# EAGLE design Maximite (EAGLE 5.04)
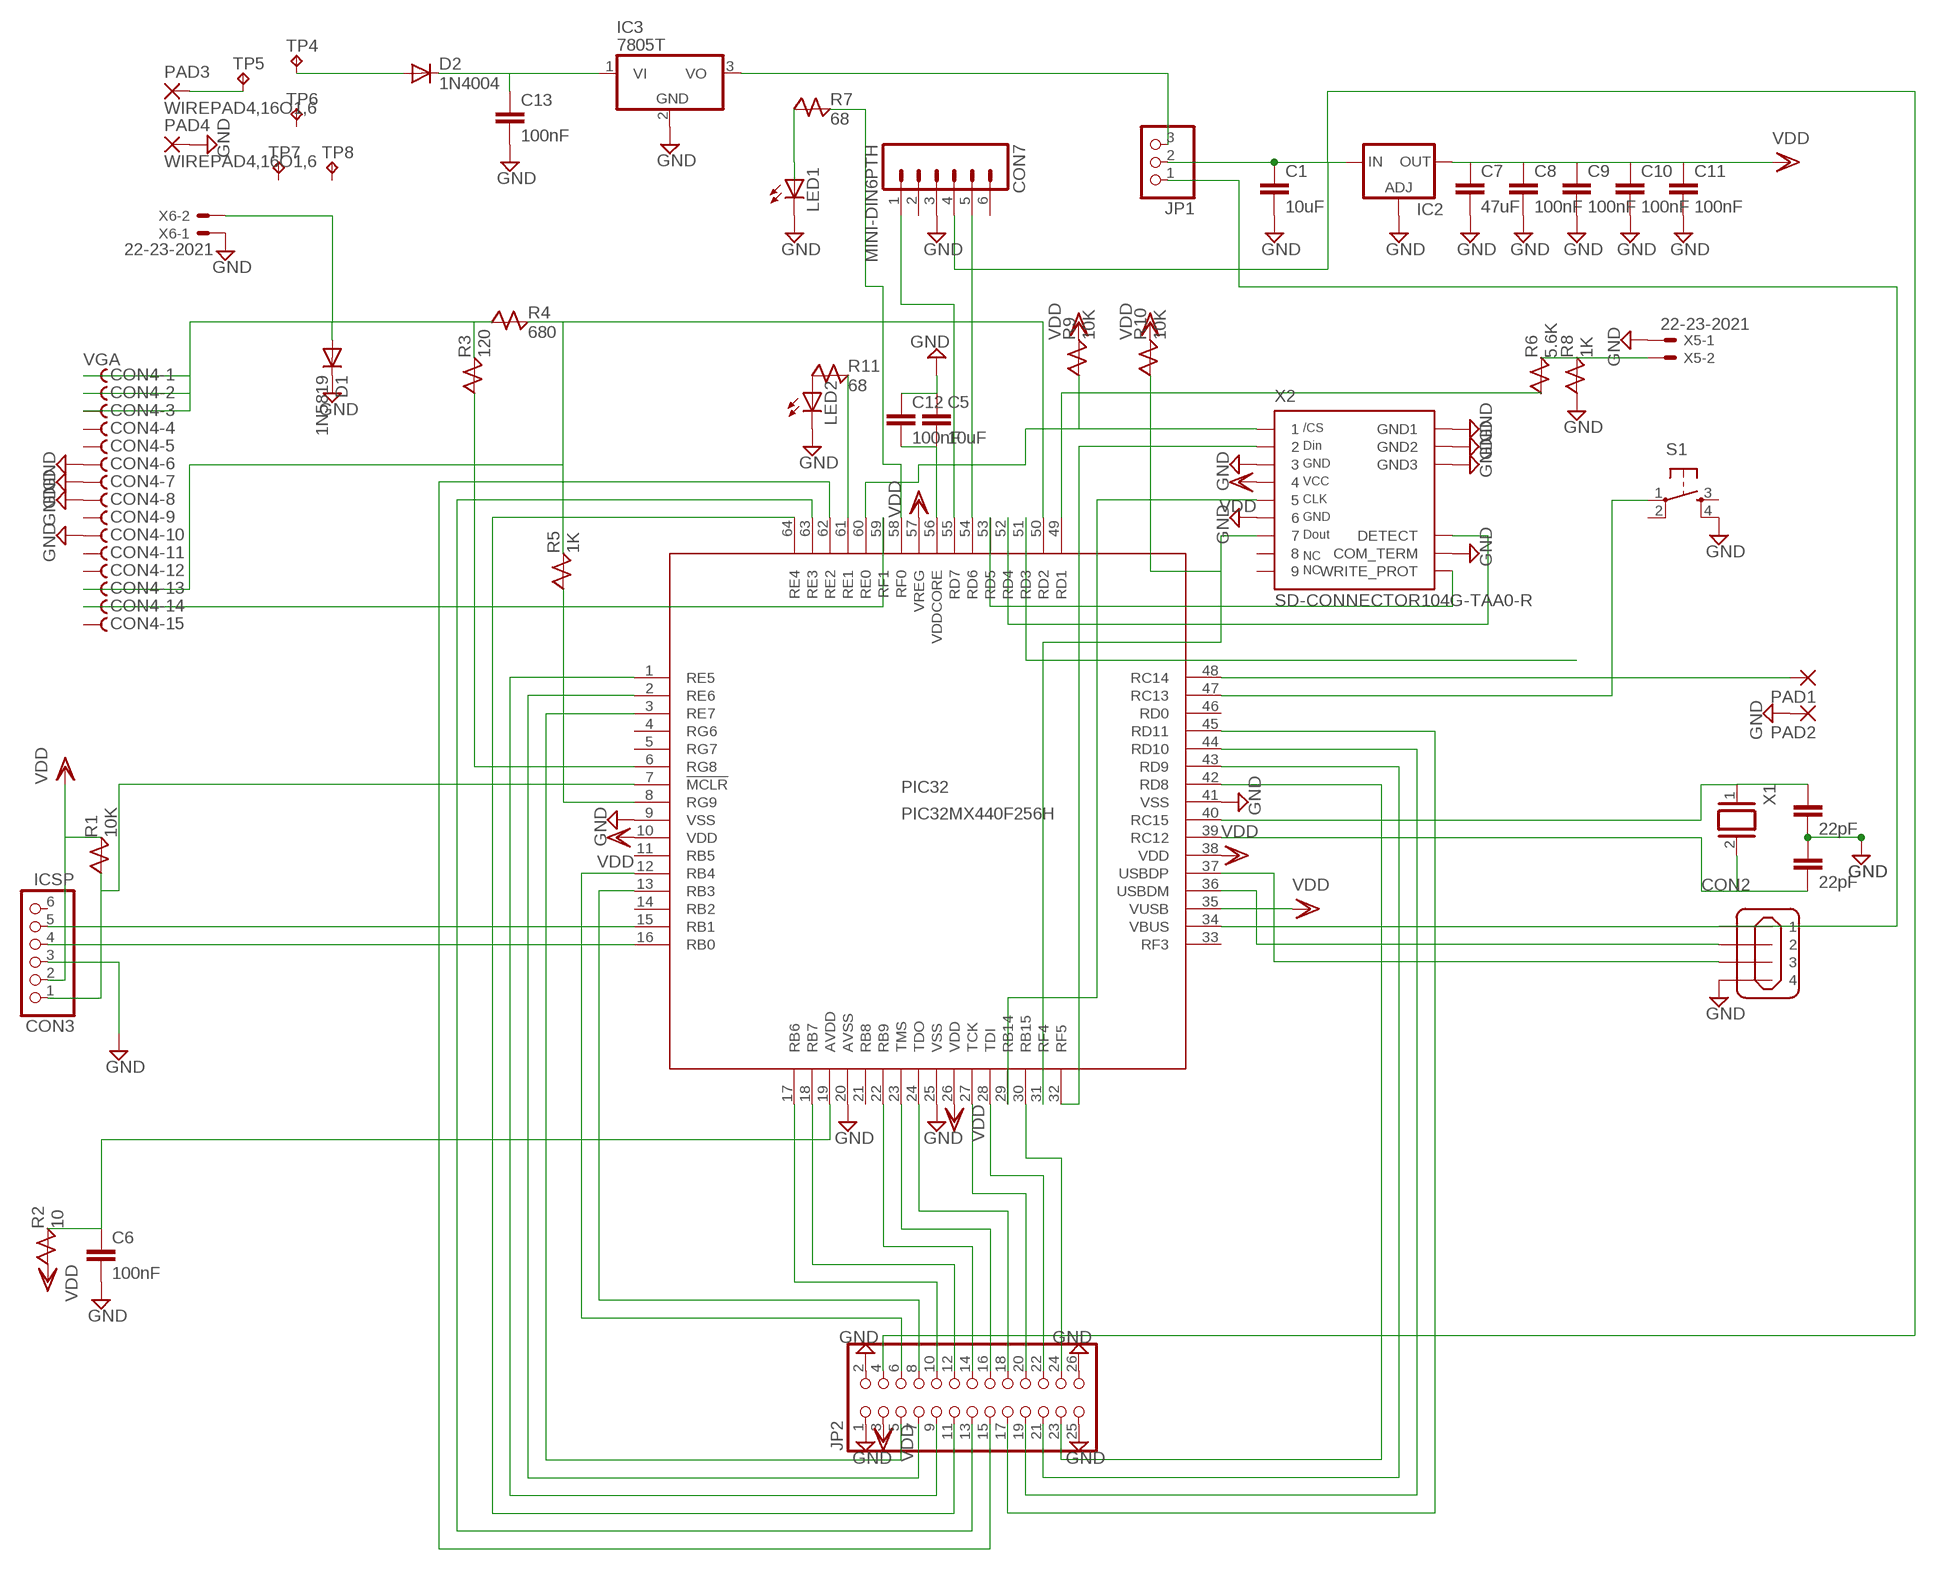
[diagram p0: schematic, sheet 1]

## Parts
C1  10uF  C5/2.5  [C5B2.5]
C3  22pF  C5/2.5  [C5B2.5]
C4  22pF  C5/2.5  [C5B2.5]
C5  10uF  C5/2.5  [C5B2.5]
C6  100nF  C5/2.5  [C5B2.5]
C7  47uF  C5/2.5  [C5B2.5]
C8  100nF  C5/2.5  [C5B2.5]
C9  100nF  C5/2.5  [C5B2.5]
C10  100nF  C5/2.5  [C5B2.5]
C11  100nF  C5/2.5  [C5B2.5]
C12  100nF  C5/2.5  [C5B2.5]
C13  100nF  C5/2.5  [C5B2.5]
CON2  MINI-USB_SHIELD4P-85-32004-10X  [85-32004-10X]
CON3  ICSP  PINHD-1X6  [1X06]
CON4  VGA  D-SUB15-HDR15RA  [HDR15RA]
CON7  MINI-DIN6PTH  [MINI-DIN6]
D1  1N5819  1N4148DO35-10  [DO35-10]
D2  1N4004  1N4148DO35-10  [DO35-10]
IC2  LM317TL  [317TL]
IC3  7805T  [TO220H]
JP1  PINHD-1X3  [1X03]
JP2  PINHD-2X13  [2X13]
LED1  LED3MM  [LED3MM]
LED2  LED3MM  [LED3MM]
PAD1  1,6/0,8  [1,6/0,8]
PAD2  1,6/0,8  [1,6/0,8]
PAD3  WIREPAD4,16O1,6  [4,16O1,6]
PAD4  WIREPAD4,16O1,6  [4,16O1,6]
PIC32  PIC32MX440F256H  [TQFP64-10X10]
R1  10K  1N4148DO35-10  [DO35-10]
R2  10  1N4148DO35-10  [DO35-10]
R3  120  1N4148DO35-10  [DO35-10]
R4  680  1N4148DO35-10  [DO35-10]
R5  1K  1N4148DO35-10  [DO35-10]
R6  5.6K  1N4148DO35-10  [DO35-10]
R7  68  1N4148DO35-10  [DO35-10]
R8  1K  1N4148DO35-10  [DO35-10]
R9  10K  1N4148DO35-10  [DO35-10]
R10  10K  1N4148DO35-10  [DO35-10]
R11  68  1N4148DO35-10  [DO35-10]
S1  TAC_SWITCHPTH  [TACTILE-PTH]
TP4  TPPAD1-13Y  [P1-13Y]
TP5  TPPAD1-13Y  [P1-13Y]
TP6  TPPAD1-13Y  [P1-13Y]
TP7  TPPAD1-17Y  [P1-17Y]
TP8  TPPAD1-17Y  [P1-17Y]
X1  XTAL/S  [QS]
X2  SD-CONNECTOR104G-TAA0-R  [104G-TAA0-R]
X5  22-23-2021  [22-23-2021]
X6  22-23-2021  [22-23-2021]

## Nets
GND: C1.2 C3.1 C4.2 C5.1 C6.2 C7.2 C8.2 C9.2 C10.2 C11.2 C12.1 C13.2 CON2.4 CON3.3 CON4.6 CON4.7 CON4.8 CON4.10 CON7.3 D1.C IC2.1(ADJ) IC3.2(GND) JP2.1 JP2.2 JP2.25 JP2.26 LED1.K(C) LED2.K(C) PAD2.1(P) PAD4.1(P) PIC32.9(VSS) PIC32.20(AVSS) PIC32.25(VSS) PIC32.41(VSS) R8.A S1.4 X2.3 X2.6 X2.COMMON(COM_TERM) X2.GND1 X2.GND2 X2.GND3 X5.1 X6.1
N$1: C3.2 PIC32.39(RC12) X1.2
N$2: CON2.1 JP1.1 PIC32.34(VBUS)
N$3: CON2.2 PIC32.36(USBDM)
N$4: CON2.3 PIC32.37(USBDP)
N$5: CON7.1 PIC32.55(RD7)
N$6: CON3.5 PIC32.15(RB1)
N$7: CON3.4 PIC32.16(RB0)
N$8: CON3.1 PIC32.7(!MCLR) R1.A
N$9: PIC32.47(RC13) S1.1
N$10: C5.2 C12.2 PIC32.56(VDDCORE)
N$11: PIC32.6(RG8) R3.A
N$12: C6.1 PIC32.19(AVDD) R2.C
N$13: CON4.14 PIC32.59(RF1)
N$14: PAD1.1(P) PIC32.48(RC14)
N$15: PIC32.49(RD1) R6.A
N$16: R6.C R8.C X5.2
N$17: CON4.1 CON4.2 CON4.3 D1.A R3.C R4.A X6.2
N$18: PIC32.8(RG9) R5.A
N$19: CON4.13 PIC32.50(RD2) R4.C R5.C
N$20: PIC32.52(RD4) X2.CD(DETECT)
N$21: LED1.A R7.A
N$22: PIC32.58(RF0) R7.C
N$23: PIC32.31(RF4) R10.A X2.7
N$24: CON7.5 PIC32.54(RD6)
N$25: PIC32.32(RF5) X2.2
N$26: IC3.3(VO) JP1.3
N$27: PIC32.51(RD3)
N$28: PIC32.29(RB14) X2.5
N$29: PIC32.53(RD5) X2.WRITE_PROTECT(WRITE_PROT)
N$30: PIC32.60(RE0) R9.A X2.1
N$31: JP2.23 PIC32.42(RD8)
N$32: JP2.21 PIC32.43(RD9)
N$33: JP2.19 PIC32.44(RD10)
N$34: JP2.17 PIC32.45(RD11)
N$35: JP2.5 PIC32.3(RE7)
N$36: C1.1 CON7.4 IC2.3(IN) JP1.2 JP2.4
N$37: JP2.24 PIC32.30(RB15)
N$38: JP2.7 PIC32.2(RE6)
N$39: JP2.9 PIC32.1(RE5)
N$40: JP2.11 PIC32.64(RE4)
N$41: JP2.13 PIC32.63(RE3)
N$42: JP2.8 PIC32.13(RB3)
N$43: C4.1 PIC32.40(RC15) X1.1
N$44: JP2.6 PIC32.12(RB4)
N$45: JP2.10 PIC32.17(RB6)
N$46: JP2.12 PIC32.18(RB7)
N$47: PAD3.1(P) TP5.1(TP)
N$48: C13.1 D2.C IC3.1(VI)
N$49: JP2.18 PIC32.24(TDO)
N$50: JP2.16 PIC32.23(TMS)
N$51: JP2.14 PIC32.22(RB9)
N$52: JP2.22 PIC32.28(TDI)
N$53: JP2.20 PIC32.27(TCK)
N$54: LED2.A R11.A
N$55: PIC32.61(RE1) R11.C
N$56: D2.A TP4.1(TP)
N$57: JP2.15 PIC32.62(RE2)
VDD: C7.1 C8.1 C9.1 C10.1 C11.1 CON3.2 IC2.2(OUT) JP2.3 PIC32.10(VDD) PIC32.26(VDD) PIC32.35(VUSB) PIC32.38(VDD) PIC32.57(VREG) R1.C R2.A R9.C R10.C X2.4
Unconnected: CON2.M1(S1) CON2.M2(S2) CON3.6 CON4.4 CON4.5 CON4.9 CON4.11 CON4.12 CON4.15 CON7.2 CON7.6 PIC32.4(RG6) PIC32.5(RG7) PIC32.11(RB5) PIC32.14(RB2) PIC32.21(RB8) PIC32.33(RF3) PIC32.46(RD0) S1.2 S1.3 TP6.1(TP) TP7.1(TP) TP8.1(TP) X2.8 X2.9

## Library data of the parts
C1 C3-C13 = capacitor-wima:C: CAPACITOR
CON2 = con-cypressindustries:MINI-USB_SHIELD4P-: MINI USB 4 Pol. Source: www.cypressindustries.com
CON3 = pinhead:PINHD-1X6: PIN HEADER
CON4 = con-thomas-betts:D-SUB15-: D-Subminiatur Connector Source: Electronioc Interconnects European Edition 1998
CON7 = SparkFun:MINI-DIN6: mini DIN 6 Connector Commonly found on the back of a computer for PS2 keyboard and mice. Schematic and footprint are proven. Spark Fun Electronics SKU : PRT-08509
D1 D2 = diode:1N4148: DIODE
IC2 = v-reg:LM317TL: VOLTAGE REGULATOR
IC3 = linear:78*: Positive VOLTAGE REGULATOR Source: http://cache.national.com/ds/LM/LM78L05.pdf http://www.fairchildsemi.com/ds/LM/LM7805.pdf
JP1 = pinhead:PINHD-1X3: PIN HEADER
JP2 = pinhead:PINHD-2X13: PIN HEADER
LED1 LED2 = SparkFun:LED: LEDs
PAD1 PAD2 = wirepad:1,6/0,8: THROUGH-HOLE PAD
PAD3 PAD4 = wirepad:WIREPAD: Wire PAD connect wire on PCB
PIC32 = microchip:PIC32MX440F256H: PIC32MX440F256H edit this description Auto generated by make-symbol-device-package-bsdl.ulp Rev. 25 Source: PIC32MX440F256H.bsdl
R1-R11 = Geoff:1N4148: Resistor (Geoff's)
S1 = SparkFun:TAC_SWITCH: Momentary Switch Button commonly used for reset or general input. Spark Fun Electronics SKU : COM-00097
TP4-TP8 = testpad:TP: Test pad
X1 = special:XTAL/S: CRYSTAL
X2 = con-sd-attend:SD-CONNECTOR
X5 X6 = con-molex:22-23-2021: .100" (2.54mm) Center Header - 2 Pin

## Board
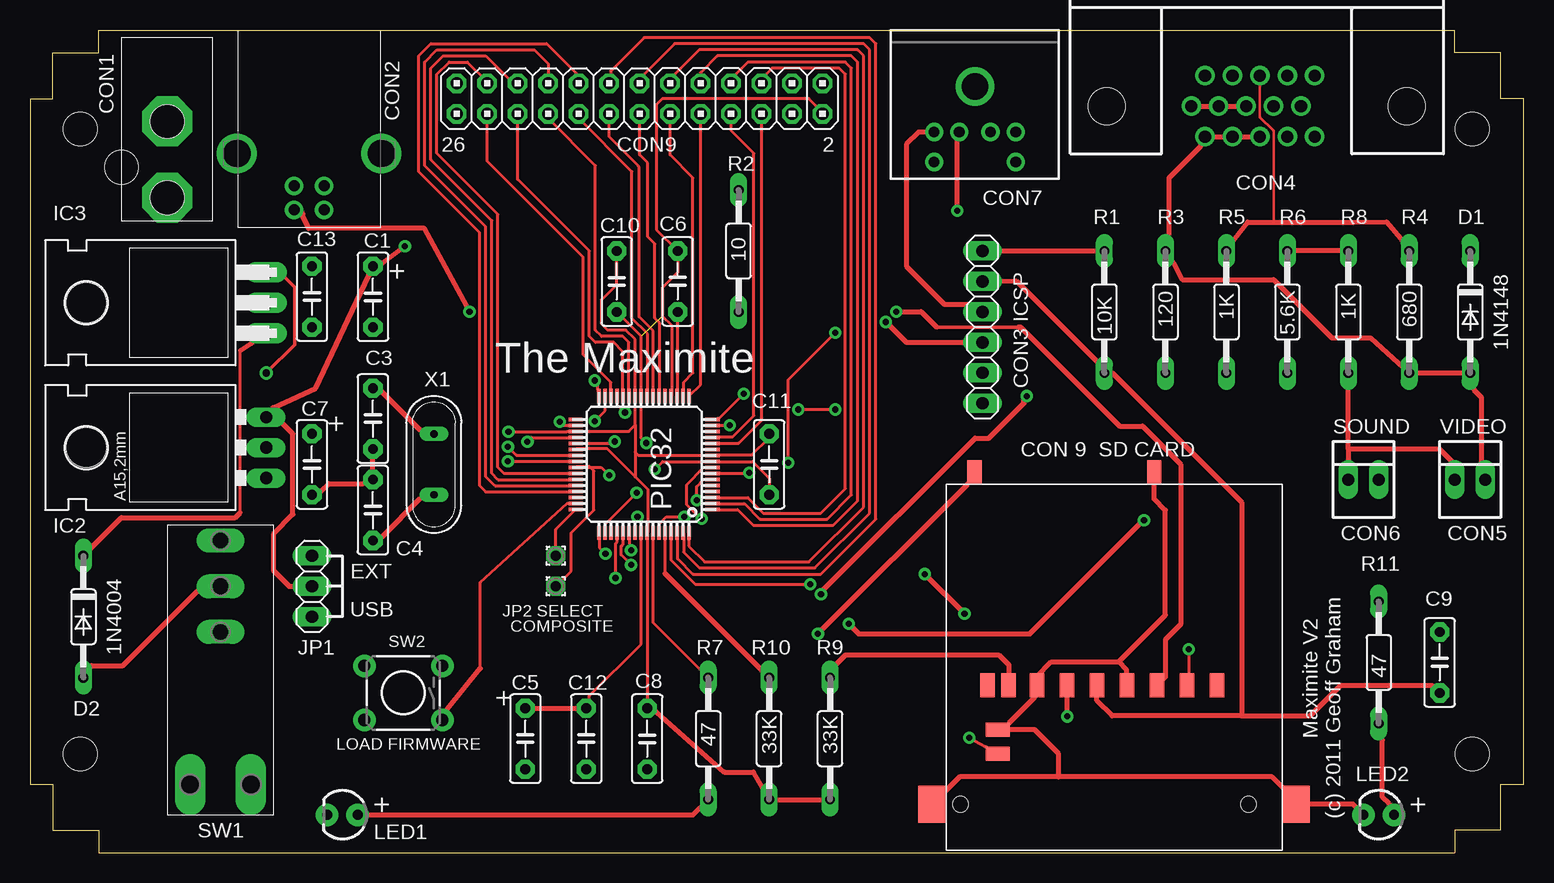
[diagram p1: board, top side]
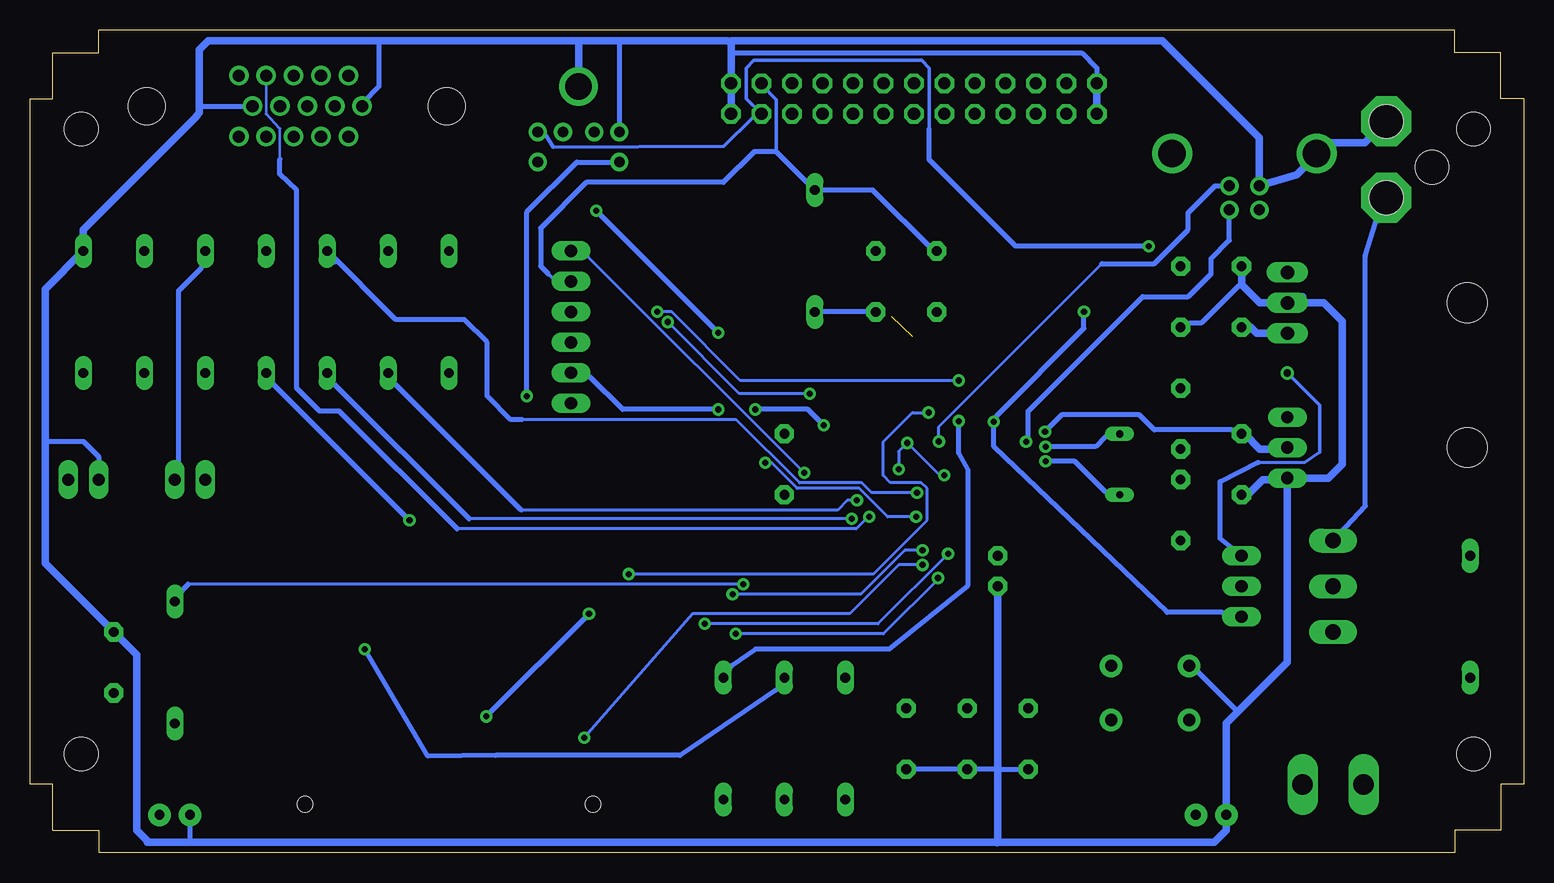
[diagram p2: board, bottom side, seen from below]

Size 124.46 x 68.58 mm. Coordinates in mm from the lower left corner, seen from the top.
Outline: 124.46,5.71 124.46,62.87 122.55,62.87 122.55,66.67 118.74,66.67 118.74,68.58 5.71,68.58 5.71,66.67 1.91,66.67 1.91,62.87 0,62.87 0,5.71 1.91,5.71 1.91,1.91 5.71,1.91 5.71,0 118.74,0 118.74,1.91 122.55,1.91 122.55,5.71 124.46,5.71
Copper layers (1*16): Top 0.035mm / dielectric 1.5mm / Bottom 0.035mm
Design rules "SparkFun": minimum track width 8mil, minimum drill 20mil, track to track 8mil, track to pad 8mil, pad to pad 8mil, via to via 8mil, smd to smd 8mil, copper to edge 10mil, drill to drill 8mil, minimum pad ring 12mil, minimum via ring 10mil, stop-mask expansion 4mil, vias tented up to drill 25mil, thermal gap 10mil
Holes 2.8 mm at 4.17,60.33 120.18,60.33 120.18,8.26 4.17,8.26 11.43,54.61 11.43,60.96 7.62,57.15
tKeepout: area 0,28.6 to 15.9,38.7; area 0,41.9 to 15.9,52.1; area 0,41.9 to 15.2,52.1; area 0,41.9 to 15.9,52.1; area 0,29.2 to 15.9,39.4
bKeepout: area 0,29.8 to 7.6,51.4
tRestrict: area 0,41.9 to 15.9,52.1; area 0,29.2 to 15.9,39.4

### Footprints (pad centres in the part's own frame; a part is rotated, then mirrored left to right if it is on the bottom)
C5B2.5 = drill 0.813 pad 1.6 octagon: 1 -2.54,0; 2 2.54,0
85-32004-10X = drill 0.92 pad 1.27 round: 1 4.71,-1.25; 2 4.71,1.25; 3 2.71,1.25; 4 2.71,-1.25 | drill 2.3 pad 3 round: M1 0,6.02; M2 0,-6.02
1X06 = drill 1.016 long: 1 -6.35,0; 2 -3.81,0; 3 -1.27,0; 4 1.27,0; 5 3.81,0; 6 6.35,0
HDR15RA = drill 1.016 round: 1 4.318,2.54; 2 2.032,2.54; 3 -0.254,2.54; 4 -2.54,2.54; 5 -4.826,2.54; 6 5.461,0; 7 3.175,0; 8 0.889,0; 9 -1.397,0; 10 -3.683,0; 11 4.318,-2.54; 12 2.032,-2.54; 13 -0.254,-2.54; 14 -2.54,-2.54; 15 -4.826,-2.54 | hole 3.048: -12.497,0; 12.497,0
MINI-DIN6 = drill 0.9 round: 1 -1.3,-8.5; 2 1.3,-8.5; 3 -3.4,-8.5; 4 3.4,-8.5; 5 -3.4,-11; 6 3.4,-11 | drill 2.2 round: P$1 0,-4.7
DO35-10 = drill 0.813 long: A 5.08,0; C -5.08,0
317TL = drill 1.016 long: 1 -2.54,-3.81; 2 0,-3.81; 3 2.54,-3.81 | hole 3.302: 0,11.176
TO220H = drill 1.118 long: 1 -2.54,-10.16; 2 0,-10.16; 3 2.54,-10.16 | hole 3.302: 0,4.826
1X03 = drill 1.016 long: 1 -2.54,0; 2 0,0; 3 2.54,0
2X13 = drill 1.016 octagon: 1 -15.24,-1.27; 2 -15.24,1.27; 3 -12.7,-1.27; 4 -12.7,1.27; 5 -10.16,-1.27; 6 -10.16,1.27; 7 -7.62,-1.27; 8 -7.62,1.27; 9 -5.08,-1.27; 10 -5.08,1.27; 11 -2.54,-1.27; 12 -2.54,1.27; 13 0,-1.27; 14 0,1.27; 15 2.54,-1.27; 16 2.54,1.27; 17 5.08,-1.27; 18 5.08,1.27; 19 7.62,-1.27; 20 7.62,1.27; 21 10.16,-1.27; 22 10.16,1.27; 23 12.7,-1.27; 24 12.7,1.27; 25 15.24,-1.27; 26 15.24,1.27
LED3MM = drill 0.813 pad 1.88 round: A -1.27,0; K 1.27,0
1,6/0,8 = drill 0.813 pad 1.6 octagon: 1 0,0
4,16O1,6 = drill 1.6 pad 4.166 octagon: 1 0,0
TQFP64-10X10 = smd 1.2 x 0.3: 1 -5.7,3.75; 2 -5.7,3.25; 3 -5.7,2.75; 4 -5.7,2.25; 5 -5.7,1.75; 6 -5.7,1.25; 7 -5.7,0.75; 8 -5.7,0.25; 9 -5.7,-0.25; 10 -5.7,-0.75; 11 -5.7,-1.25; 12 -5.7,-1.75; 13 -5.7,-2.25; 14 -5.7,-2.75; 15 -5.7,-3.25; 16 -5.7,-3.75; 33 5.7,-3.75; 34 5.7,-3.25; 35 5.7,-2.75; 36 5.7,-2.25; 37 5.7,-1.75; 38 5.7,-1.25; 39 5.7,-0.75; 40 5.7,-0.25; 41 5.7,0.25; 42 5.7,0.75; 43 5.7,1.25; 44 5.7,1.75; 45 5.7,2.25; 46 5.7,2.75; 47 5.7,3.25; 48 5.7,3.75 | smd 0.3 x 1.2: 17 -3.75,-5.7; 18 -3.25,-5.7; 19 -2.75,-5.7; 20 -2.25,-5.7; 21 -1.75,-5.7; 22 -1.25,-5.7; 23 -0.75,-5.7; 24 -0.25,-5.7; 25 0.25,-5.7; 26 0.75,-5.7; 27 1.25,-5.7; 28 1.75,-5.7; 29 2.25,-5.7; 30 2.75,-5.7; 31 3.25,-5.7; 32 3.75,-5.7; 49 3.75,5.7; 50 3.25,5.7; 51 2.75,5.7; 52 2.25,5.7; 53 1.75,5.7; 54 1.25,5.7; 55 0.75,5.7; 56 0.25,5.7; 57 -0.25,5.7; 58 -0.75,5.7; 59 -1.25,5.7; 60 -1.75,5.7; 61 -2.25,5.7; 62 -2.75,5.7; 63 -3.25,5.7; 64 -3.75,5.7
TACTILE-PTH = drill 1.016 pad 1.88 round: 1 -3.251,2.261; 2 3.251,2.261; 3 -3.251,-2.261; 4 3.251,-2.261
P1-13Y = drill 1.321 pad 1.905 long: 1 0,0
P1-17Y = drill 1.702 pad 2.121 long: 1 0,0
QS = drill 0.61 long: 1 -2.54,0; 2 2.54,0
104G-TAA0-R = smd 1.2 x 2: 1 6.87,0; 2 4.37,0; 3 1.87,0; 4 -0.63,0; 5 -3.13,0; 6 -5.63,0; 7 -8,0; 8 -9.75,0; 9 9.37,0; CD -10.83,17.75; GND2 4.15,17.75 | smd 2 x 1.2: COMMON -8.9,-3.7; WRITE_PROTECT -8.9,-5.7 | smd 2.3 x 3.1: GND1 -14.35,-9.9; GND3 15.95,-9.9 | hole 1.3: -12,-9.9; 12,-9.9
22-23-2021 = drill 1 long: 1 -1.27,0; 2 1.27,0

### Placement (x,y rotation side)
C1  28.57,46.36 270 top
C3  28.57,36.2 90 top
C4  28.57,28.57 90 top
C5  41.27,9.53 90 top
C6  53.98,47.62 90 top
C7  23.49,32.39 270 top
C8  51.44,9.53 270 top
C9  117.47,15.88 90 top
C10  48.9,47.62 270 top
C11  61.59,32.39 270 top
C12  46.36,9.53 90 top
C13  23.49,46.36 90 top
CON2  23.26,58.29 270 top
CON3  79.38,43.82 270 top
CON4  102.23,62.23 180 top
CON7  78.74,68.58 0 top
D1  120.02,45.09 270 top
D2  4.45,19.68 270 top
IC2  15.88,33.78 90 top
IC3  9.53,45.85 90 top
JP1  23.49,22.22 90 top
JP2  50.8,62.87 180 top
LED1  26.04,3.17 180 top
LED2  112.39,3.17 180 top
PAD1  43.82,24.76 0 top
PAD2  43.82,22.22 0 top
PAD3  11.43,54.61 0 top
PAD4  11.43,60.96 0 top
PIC32  51.18,32.39 180 top
R1  89.53,45.09 90 top
R2  59.05,50.16 90 top
R3  94.61,45.09 270 top
R4  114.93,45.09 270 top
R5  99.69,45.09 270 top
R6  104.77,45.09 270 top
R7  56.52,9.53 270 top
R8  109.85,45.09 270 top
R9  61.59,9.53 90 top
R10  66.67,9.53 90 top
R11  112.39,15.88 270 top
S1  31.11,13.34 180 top
TP4  15.88,22.22 90 top
TP5  15.88,26.04 90 top
TP6  15.88,18.41 90 top
TP7  13.34,5.71 180 top
TP8  18.41,5.71 0 top
X1  33.66,32.39 90 top
X2  89.53,13.97 0 top
X5  111.12,31.11 0 top
X6  120.02,31.11 0 top

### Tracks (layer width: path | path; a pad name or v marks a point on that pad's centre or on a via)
GND  (via drill 0.51)  (1 unrouted)
  Top 0.254: C10.2 50.93,43.05 PIC32.25 50.93,34.6 v51.37,34.16 | PIC32.20 53.47,38.12 53.47,43.97 52.71,44.73 52.71,47.12 53.98,48.39 C6.2 52.2,51.94 52.2,62.36 52.71,62.87 64.9,62.87 66.04,61.72 JP2.2 | C11.2 61.59,31.23 60.22,32.62 56.9,32.62 PIC32.9 56.85,32.66 56.37,32.66 56.32,32.62 52.72,32.62 v52.07,31.96 | PAD2.1 45.09,23.49 45.09,26.67 46.99,28.57 46.99,31.84 46.66,32.16 45.51,32.16 PIC32.41 47.59,32.14 v48.27,31.46 | X2.COMMON 81.61,10.85 | 83.74,12.98 X2.6 | 93.67,30.73 X2.GND2 | 27.79,30.79 C4.2 | C7.2 24.28,30.17
  Top 0.305: X2.GND1 | 105.41,4.45 105.41,4.15 X2.GND3
  Top 0.406: X2.GND3 110.23,4.07 LED2.K | 81.61,10.85 83.74,12.98 | 109.85,33.66 R8.A | C4.2 C3.1 | CON4.8 CON4.7 CON4.6 | 27.79,30.79 24.89,30.79 24.28,30.17 | X2.GND1 77.47,6.35 85.72,6.35 | 85.72,6.35 103.5,6.35 105.41,4.45 | X2.COMMON 83.71,10.27 85.72,8.26 85.72,6.35 | X2.6 83.91,14.71 85.11,15.92 90.71,15.92 | 90.71,15.92 91.36,15.27 91.36,14.01 X2.3 | 109.85,33.66 X5.1 | 109.85,33.66 117.47,33.66 118.74,32.39 X6.1 | CON7.3 74.05,60.08 73.02,59.05 73.02,48.9 76.2,45.72 78.74,45.72 CON3.3 | 93.67,30.73 93.67,29.51 94.61,28.57 94.61,19.81 90.71,15.92
  Bottom 0.254: 96.77,62.26 CON4.6 96.77,62.48 | 27.79,44.15 C1.2 | 23.49,47.37 23.77,47.24 | v48.27,31.46 48.66,31.46 v51.37,34.16 52.07,33.47 v52.07,31.96
  Bottom 0.305: 27.66,15.6 S1.4
  Bottom 0.406: 23.81,11.75 27.66,15.6 | C5.1 43.82,6.99 C12.1 C8.2 | 96.77,62.48 95.38,63.88 95.38,67.69 | 27.79,44.15 26.87,44.15 23.77,47.24 | 110.36,62.23 CON4.10 | 111.12,0.89 LED2.K | X6.1 118.74,33.02 120.02,34.29 123.19,34.29 | CON7.3 75.34,67.47 75.56,67.69 | JP2.25 35.56,65.41 36.83,66.67 66.04,66.67
  Bottom 0.61: JP2.25 JP2.26 | JP2.2 JP2.1 66.04,66.67 66.04,67.44 | IC2.1 19.68,15.88 23.81,11.75 24.76,10.79 LED1.K 24.76,1.91 25.78,0.89 111.12,0.89 114.68,0.89 114.68,1.02 115.57,1.91 115.57,16.51 C9.2 123.19,24.13 123.19,34.29 123.19,46.99 D1.C 120.02,51.94 110.62,61.34 110.62,61.41 110.36,61.66 110.36,62.23 | 110.36,62.23 110.36,65.66 | PAD2.1 43.82,6.99 43.82,1.01 43.87,0.97 43.87,0.86 | 11.37,62.57 11.37,61.02 PAD4.1 13.22,59.16 16.26,59.16 18.89,56.54 18.9,56.54 CON2.4 22.01,59.6 30.1,67.69 65.91,67.69 | IC3.2 19.67,46.37 18.41,46.37 18.42,46.36 | 110.36,62.23 110.36,66.93 109.6,67.69 95.38,67.69 75.56,67.69 66.29,67.69 66.04,67.44 | 65.91,67.69 66.04,67.69 | 66.04,67.44 66.04,67.56 65.91,67.69 | IC2.1 16.26,31.24 15.11,32.39 15.11,44.32 16.64,45.85 IC3.2 | C13.2 23.49,47.37 21.97,45.85 IC3.2 | C7.2 22.99,29.84 21.72,31.11 19.81,31.11 IC2.1
N$1  (via drill 0.51)
  Top 0.254: v39.83,33.86 40.54,33.15 44.88,33.15 PIC32.39
  Top 0.406: C3.2 29.36,38.41 32.54,35.23 X1.2
  Bottom 0.406: v39.83,33.86 35.66,33.86 34.85,34.67 X1.2
N$2  (via drill 0.51)
  Top 0.254: v44.15,35.94 44.45,35.64 44.88,35.64 PIC32.34 | 22.63,53.26 22.76,53.26
  Top 0.406: 22.63,53.26 23.22,52.05 32.87,52.05 v36.63,45.11 | 22.76,53.26 CON2.1
  Bottom 0.254: JP1.1 25.09,20.04 | v44.15,35.94 43.92,36.42
  Bottom 0.406: v44.15,35.94 44.15,33.86 29.69,20.04 25.09,20.04 | v36.63,45.11 36.63,43.71 43.92,36.42
N$3  (via drill 0.51)
  Top 0.254: v41.45,34.27 41.81,34.62 44.88,34.62 PIC32.36
  Bottom 0.254: v41.45,34.27 41.45,34.72
  Bottom 0.406: CON2.2 24.51,51.06 26.04,49.53 26.04,48.26 27.94,46.36 31.75,46.36 41.27,36.83 41.27,34.44 v41.45,34.27
N$4  (via drill 0.51)
  Top 0.254: v48.72,34.29 48.57,34.14 46.08,34.14 PIC32.37
  Bottom 0.254: v48.72,34.29 48.72,35.54 35.15,49.1
  Bottom 0.406: CON2.3 25.7,55.58 27.94,53.34 27.94,51.94 30.76,49.12 35.14,49.12 35.15,49.1
N$5  (via drill 0.51)
  Top 0.254: v50.62,28.02 50.44,27.84 50.44,27.28 PIC32.55 | v63.2,32.51 63.2,39.45 v67.11,43.36
  Top 0.406: v77.27,53.52 77.27,59.33 CON7.1
  Bottom 0.254: v50.62,28.02 52.98,28.02 55.35,30.38 60.53,30.38 62.66,32.51 v63.2,32.51
  Bottom 0.406: v67.11,43.36 v77.27,53.52
N$6  (via drill 0.51)
  Top 0.254: v58.32,35.64 57.48,35.64 PIC32.15 | v64.03,36.96 v67.11,36.96
  Bottom 0.406: v67.11,36.96 75.08,36.96 77.77,39.65 CON3.5 | v64.03,36.96 59.64,36.96 v58.32,35.64
N$7  (via drill 0.51)
  Top 0.254: v59.49,38.28 57.48,36.27 PIC32.16
  Top 0.406: v71.32,44.25 73.02,42.55 CON3.4
  Bottom 0.254: v59.49,38.28 65.35,38.28 v71.32,44.25
N$8  (via drill 0.51)
  Top 0.254: v59.94,31.67 59.92,31.65 57.48,31.65 PIC32.7
  Top 0.406: CON3.1 R1.A
  Bottom 0.254: v59.94,31.67 77.93,49.66 CON3.1
N$9
  Top 0.254: 37.54,15.39 37.54,22.55 44.76,29.13 44.88,29.13 PIC32.47 | S1.1 34.77,11.99
  Top 0.406: 34.77,11.99 37.54,15.39
N$10
  Top 0.254: PIC32.56 50.93,17.4 46.61,13.08 46.61,12.32 C12.2
  Top 0.406: C5.2 C12.2
N$11  (via drill 0.51)
  Top 0.254: v55.55,29.39 55.55,30.53 56.16,31.14 56.29,31.14 PIC32.6
  Bottom 0.254: 93.93,38.99 R3.A | v55.55,29.39 56.34,29.39 57.15,28.57 83.52,28.57
  Bottom 0.406: 83.52,28.57 93.93,38.99
N$12
  Top 0.254: C6.1 53.98,38.13 PIC32.19
  Bottom 0.406: C6.1 R2.C
N$13  (via drill 0.51)
  Top 0.254: v54.53,28.02 53.04,28.02 52.43,27.41 52.43,27.28 PIC32.59
  Bottom 0.203: 104.77,61.59 CON4.14 | 103.63,57.82 103.63,60.36
  Bottom 0.254: v54.53,28.02 54.61,28.02 55.63,27 88.88,27 | 103.63,60.36 104.77,61.59
  Bottom 0.406: 103.63,57.82 103.66,56.57 102.23,55.25 102.23,38.73 100.33,36.83 98.7,36.83 88.88,27
N$14
  Top 0.254: PAD1.1 43.82,26.97 PIC32.48
N$15  (via drill 0.51)
  Top 0.254: v47.96,24.94 47.45,25.45 47.45,26.09 PIC32.49
  Top 0.406: v92.84,27.74 92.79,27.74 83.31,18.26 69.06,18.26 v68.22,19.1
  Bottom 0.254: v47.96,24.94 53.8,19.1 v68.22,19.1
  Bottom 0.406: v92.84,27.74 104.09,38.99 R6.A
N$16
  Top 0.406: R8.C R6.C
  Bottom 0.406: X5.2 112.06,32.72 112.06,46.86 110.16,48.77 R8.C
N$17
  Top 0.254: R3.C 94.92,51.56
  Top 0.406: X6.2 120.95,32.72 120.95,37.97 120.32,38.61 D1.A R4.A 111.71,42.93 108.48,42.93 103.63,47.78 96.04,47.78 95.3,49.15 R3.C | CON4.3 CON4.2 CON4.1 97.56,58.9 94.92,56.26 94.92,51.56
N$18  (via drill 0.51)
  Top 0.254: v55.98,27.84 55.91,27.84 54.71,29.03 54.71,30.68 56.16,32.13 56.29,32.13 PIC32.8
  Bottom 0.254: v55.98,27.84 87.86,27.84 | 99.01,38.99 R5.A
  Bottom 0.406: 87.86,27.84 99.01,38.99
N$19  (via drill 0.51)
  Top 0.203: 102.49,61.32 CON4.13 | 103.63,52.55 103.63,60.17
  Top 0.254: v50.55,30.02 47.93,27.41 47.93,27.28 PIC32.50 | 103.63,60.17 102.49,61.32
  Top 0.406: R4.C 114.25,51.18 113.02,52.58 110.29,52.55 103.63,52.55 101.47,52.57 100.38,51.18 R5.C
  Bottom 0.254: v50.55,30.02 54.33,30.02 55.14,30.84 60.33,30.84 65.61,36.12 83.46,36.12 | R5.C 99.01,49.15
  Bottom 0.406: 83.46,36.12 84.38,36.12 86.36,38.1 86.36,42.55 88.27,44.45 93.98,44.45 R5.C
N$20  (via drill 0.51)
  Top 0.254: v48.79,22.91 48.79,25.78 48.92,25.91 48.92,26.09 PIC32.52 | 78.13,30.73 X2.CD
  Top 0.406: v65.66,18.26 78.13,30.73
  Bottom 0.254: v48.79,22.91 48.69,22.91 53.34,18.26 v65.66,18.26
N$21
  Top 0.406: LED1.A 55.25,3.17 R7.A
N$22
  Top 0.254: PIC32.58 51.93,19.19 R7.C
N$23  (via drill 0.51)
  Top 0.254: v47.07,35.99 47.93,36.86 47.93,37.49 PIC32.31
  Top 0.406: R10.A 66.67,15.22 67.96,16.51 80.71,16.51 81.56,15.67 81.56,14 X2.7
  Bottom 0.406: v47.07,35.99 47.07,33.35 46.28,31.93 46.28,22.33 52.88,16.99 63.98,16.99 65.99,15.62 R10.A
N$24  (via drill 0.51)
  Top 0.254: v50.09,25.22 49.94,25.38 49.94,26.09 PIC32.54
  Top 0.406: v65.91,21.56 65.91,21.71 78.77,34.57 79.91,34.57 82.81,37.47 82.81,37.83 v83.06,38.08
  Bottom 0.254: v50.09,25.22 51.56,25.22 55.22,21.56 v65.91,21.56
  Bottom 0.406: v83.06,38.08 83.06,53.42 78.89,57.58 CON7.5
N$25  (via drill 0.51)
  Top 0.254: v47.07,39.37 47.3,39.14 47.3,38.68 PIC32.32
  Top 0.305: 75.56,43.82 82.36,43.82
  Top 0.406: v72.19,45.11 74.27,45.11 75.56,43.82 | 82.36,43.82 82.55,43.82 90.8,35.56 92.71,35.56 95.88,32.39 95.88,19.05 94.61,17.78 94.61,14.68 X2.2
  Bottom 0.254: v47.07,39.37 65.25,39.37 70.99,45.11 v72.19,45.11
N$26  (via drill 0.6)
  Top 0.305: v19.68,40.01 19.7,40.01 22.06,42.37 22.06,47.15 20.95,48.26 19.81,48.26 IC3.3
  Bottom 0.254: 22.1,32.54 18.19,32.54 16.99,33.4
  Bottom 0.305: 16.99,33.4 16.99,37.31 v19.68,40.01
  Bottom 0.406: 22.1,32.54 25.27,30.94 25.27,26.19 JP1.3
N$28  (via drill 0.51)
  Top 0.254: v49.58,36.7 48.95,37.34 48.95,37.49 PIC32.29 | 86.46,13.31 X2.5
  Top 0.406: v74.57,23.24 v77.88,19.94 | v86.44,11.38 86.44,13.28 86.46,13.31
  Bottom 0.254: v74.57,23.24 54.2,23.24 49.71,27.74 49.71,30.38 50.19,30.86 51.05,30.86 51.06,30.86 52.77,30.86 53.37,31.46 53.37,34.27 50.93,36.7 v49.58,36.7
  Bottom 0.406: v77.88,19.94 v86.44,11.38
N$29  (via drill 0.51)
  Top 0.254: v50.09,24 49.25,24.84 49.25,25.58 49.43,25.76 49.43,26.09 PIC32.53 | v78.28,9.6 79.65,8.87 X2.WRITE_PROTECT
  Bottom 0.254: v50.09,24 52.07,24 56.13,19.94 69.21,19.94 v78.28,9.6
N$30  (via drill 0.51)
  Top 0.254: 52.93,23.27 PIC32.60 | v96.57,16.97 96.57,14.96 X2.1
  Top 0.406: R9.A 52.93,23.27
  Bottom 0.254: 62.28,13.59 R9.A
  Bottom 0.406: v96.57,16.97 91.31,8.08 85.65,8.13 70.28,8.13 62.28,13.59
N$31
  Top 0.254: JP2.23 38.1,64.26 36.45,65.91 34.93,65.91 33.91,64.9 33.91,58.29 38.99,53.21 38.99,32.13 39.5,31.62 45.47,31.62 PIC32.42
N$32
  Top 0.254: JP2.21 40.26,64.13 37.97,66.42 34.42,66.42 33.4,65.41 33.4,57.79 38.48,52.71 38.48,31.62 38.99,31.11 45.46,31.11 PIC32.43
N$33
  Top 0.254: JP2.19 43.18,65.79 42.04,66.93 33.91,66.93 32.89,65.91 32.89,57.28 37.97,52.2 37.97,31.37 38.73,30.61 45.45,30.61 PIC32.44
N$34
  Top 0.254: JP2.17 45.72,64.77 43.05,67.44 33.4,67.44 32.39,66.42 32.39,56.77 37.47,51.69 37.47,30.61 37.97,30.1 45.45,30.1 PIC32.45
N$35
  Top 0.254: PIC32.3 56.9,29.61 59.82,29.61 59.82,29.59 61.09,28.32 65.91,28.32 67.94,30.35 67.94,64.9 67.44,65.41 61.85,65.41 60.96,64.52 JP2.5
N$36  (via drill 0.51)
  Top 0.406: v31.24,50.57 28.73,48.69 C1.1 28.24,48.11 23.8,38.73 20.27,37.11 IC2.3 20.51,36.32 21.91,34.91 21.91,28.21 20.31,26.61 20.31,23.5 21.59,22.22 JP1.2
  Bottom 0.254: 81.43,59.77 81.41,59.77
  Bottom 0.305: 81.43,59.77 80.84,58.83 66.65,58.88 64.29,61.24 JP2.4 64.77,62.87 64.77,65.41 64.13,66.04 50.16,66.04 49.53,65.41 49.53,60.33 | 81.41,59.77 CON7.4
  Bottom 0.406: v31.24,50.57 42.32,50.57 49.53,57.79 49.53,60.33
N$37
  Top 0.254: JP2.24 38.1,57.66 46.1,49.66 46.1,41.53 48.41,39.22 48.41,38.1 PIC32.30
N$38
  Top 0.254: PIC32.2 56.9,29.11 59.52,29.11 59.55,29.08 59.56,29.08 60.83,27.81 66.42,27.81 68.45,29.84 68.45,65.41 67.94,65.91 59.82,65.91 58.42,64.52 JP2.7
N$39
  Top 0.254: PIC32.1 56.9,28.61 58.97,28.61 60.27,27.3 66.93,27.3 68.96,29.34 68.96,65.91 68.45,66.42 57.28,66.42 55.88,65.02 JP2.9
N$40
  Top 0.254: 53.34,64.01 JP2.11 53.34,64.52 55.75,66.93 68.96,66.93 69.47,66.42 69.47,28.83 64.9,24.26 56.22,24.26 54.91,25.56 54.91,26.67 PIC32.64
N$41
  Top 0.254: PIC32.63 54.47,26.65 54.47,25.06 55.78,23.75 65.41,23.75 69.98,28.32 69.98,66.93 69.47,67.44 53.72,67.44 50.8,64.52 JP2.13
N$42
  Top 0.254: JP2.8 58.42,60.2 60.33,58.29 60.33,36.45 58.55,34.67 56.92,34.67 PIC32.13
N$43  (via drill 0.51)
  Top 0.254: v39.83,32.64 44.88,32.64 PIC32.40 | C4.1 29.36,26.36 | 32.54,29.54 X1.1
  Top 0.406: 29.36,26.36 32.54,29.54
  Bottom 0.406: v39.83,32.64 37.39,32.64 34.85,30.1 X1.1
N$44
  Top 0.254: JP2.6 60.96,36.07 59.05,34.16 56.91,34.16 PIC32.12
N$45
  Top 0.254: JP2.10 55.88,39.03 PIC32.17
N$46
  Top 0.254: JP2.12 53.34,58.17 55.25,56.26 55.25,40.01 54.48,39.24 54.48,39.23 54.47,39.22 54.47,38.12 PIC32.18
N$47
  Bottom 0.406: TP5.1 13.18,28.9 13.18,49.76 12.29,52.55 PAD3.1
N$48
  Top 0.254: 17.53,41.86 17.53,30.96 17.51,30.95 17.51,28.36
  Top 0.406: 17.53,41.86 18.44,42.47 IC3.1 | D2.C 7.62,27.94 17.09,27.94 17.51,28.36
  Bottom 0.61: C13.1 22.73,43.82 22.22,43.31 IC3.1
N$49
  Top 0.254: PIC32.24 | JP2.18 45.72,61.21 50.16,56.77 50.16,44.57 51.47,43.27 51.47,38.12 PIC32.24 | PIC32.24 51.37,38.15
N$50
  Top 0.254: PIC32.23 51.94,38.1 | JP2.16 48.26,59.69 50.67,57.28 50.67,57.26 50.77,57.16 50.77,44.66 51.93,43.5 PIC32.23 | PIC32.23 51.91,38.1
N$51
  Top 0.254: PIC32.22 52.45,38.11 | JP2.14 50.8,58.17 51.47,57.5 51.47,51.37 52.07,50.77 52.07,44.57 52.47,44.16 52.47,38.12 PIC32.22 | PIC32.22 52.41,38.1
N$52
  Top 0.254: JP2.22 40.64,56.13 46.61,50.16 46.61,43.05 47.12,42.55 48.64,42.55 49.4,41.78 49.4,38.11 PIC32.28
N$53
  Top 0.254: JP2.20 43.18,61.21 47.12,57.28 47.12,43.56 47.62,43.05 49.4,43.05 49.91,42.55 49.91,38.11 PIC32.27
N$54
  Top 0.406: R11.A 112.7,9.4 112.7,4.65 113.26,4.09 LED2.A
N$55  (via drill 0.51)
  Top 0.254: v65.02,22.4 55.42,22.4 53.44,24.38 53.44,26.09 PIC32.61
  Bottom 0.254: v65.02,22.4 111.28,22.4
  Bottom 0.406: 111.28,22.4 111.71,21.97 R11.C
N$56
  Top 0.406: D2.A 5.13,15.62 7.75,15.62 13.92,21.79 TP4.1
N$57
  Top 0.254: JP2.15 48.39,64.13 48.39,65.15 51.18,67.94 69.98,67.94 70.48,67.44 70.48,27.81 65.91,23.24 55.24,23.24 53.97,24.51 53.97,26.65 PIC32.62
N$58
  Bottom 0.61: 78.74,65.19 78.74,67.64
VDD  (via drill 0.51)
  Top 0.254: C10.1 48.9,47.37 47.62,46.1 47.62,44.07 48.13,43.56 49.66,43.56 50.42,42.8 50.42,38.1 PIC32.26 50.43,35.66 | C11.1 61.59,34.59 60.16,33.16 56.91,33.16 PIC32.10 50.7,33.14 50.43,33.4 | 50.43,33.4 50.43,31.35 | 50.43,35.66 50.43,33.4 | 50.43,31.35 51.47,30.31 51.47,26.72 PIC32.57 C8.1 52.22,11.73 | 50.43,31.35 48.12,33.66 45.51,33.66 PIC32.38 | 50.43,35.66 49.9,35.14 PIC32.35 44.88,35.13 44.76,35.13 44.73,35.1 v39.88,35.1
  Top 0.406: CON3.2 82.17,47.67 88.42,41.42 88.85,41.02 R1.C 90.17,40.01 100.96,29.21 100.96,11.43 | R10.C R9.C 60.27,6.73 57.86,6.73 52.22,11.73 | X2.4 88.91,12.7 90.17,11.43 100.96,11.43 | 100.96,11.43 106.68,11.43 109.22,13.97 116.84,13.97 C9.1
  Bottom 0.254: C10.1 49.15,50.16 | C7.1 24.28,35.26
  Bottom 0.305: JP2.3 63.5,64 62.27,62.77 62.27,58.46 | 81.28,48.26 81.26,48.26 80.64,47.65 79.39,47.65 CON3.2
  Bottom 0.406: 49.15,50.16 54.23,55.25 R2.A 62.27,58.46 64.1,58.46 66.67,55.88 78.1,55.88 81.91,52.07 81.91,48.9 81.28,48.26 | 24.28,35.26 30.76,35.26 32,36.5 38.48,36.5 v39.88,35.1
  Bottom 0.61: C7.1 23.24,34.93 21.97,33.66 19.81,33.66 IC2.2

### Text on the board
tPlace: CON1 | 26 | CON9 | 2 | CON7 | IC3 | + | 1K | 1K | 10K | 120 | 5.6K | 680 | 1N4148 | C3 | The Maximite | CON3 ICSP | + | SOUND | VIDEO | CON 9 SD CARD | IC2 | CON6 | CON5 | C4 | EXT | USB | JP2 SELECT | COMPOSITE | JP1 | SW2 | 1N4004 | 47 | + | 47 | Maximite V2 | LOAD FIRMWARE | 33K | 33K | + | + | (c) 2011 Geoff Graham | SW1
